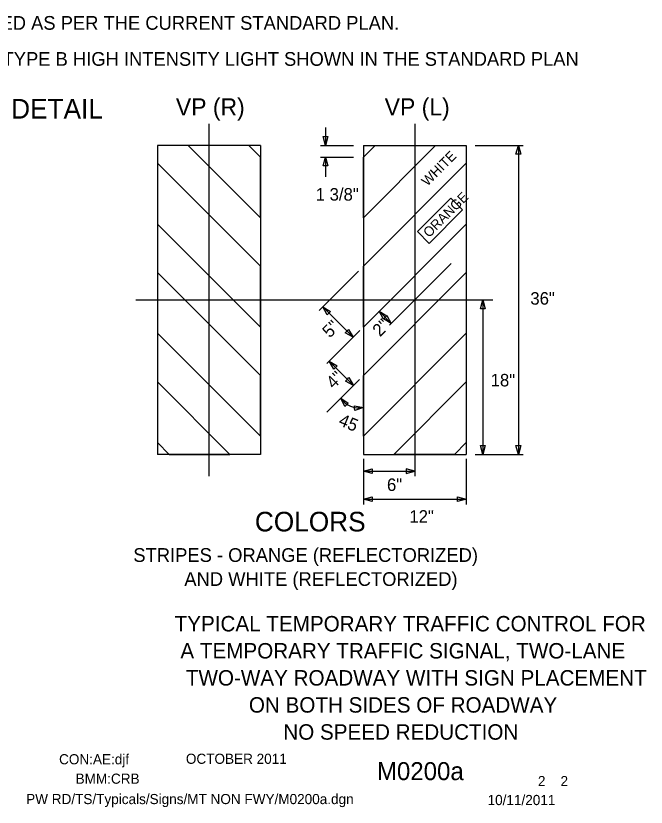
# Model space of a CAD drawing. Extents: x 16520 to 18479, y 5662 to 6927.
# Drawn here: x 18093.2 to 18479, y 5931.8 to 6415.8 of the extents above; entities that cross this region are included whole.
import ezdxf

# ---------------------------------------------------------------- set-up
doc = ezdxf.new("R2010")
doc.units = 0
for name, color, linetype in [('BORDER', 7, 'Continuous'), ('BORDER_SIGNAL_WO', 7, 'Continuous'), ('TRAFFIC_SIGNS_PR', 7, 'Continuous'), ('TYPICAL_TEXT_DIMEN_PR', 7, 'Continuous')]:
    doc.layers.add(name, color=color, linetype=linetype)

msp = doc.modelspace()

# ---------------------------------------------------------------- linework, layer by layer
at = {"layer": 'TRAFFIC_SIGNS_PR'}
for p, q in [((18242.87, 6336.58), (18179.87, 6336.58)), ((18179.87, 6336.58), (18179.87, 6147.58)), ((18242.87, 6292.31), (18198.6, 6336.58)), ((18242.87, 6329.44), (18235.73, 6336.58)), ((18242.87, 6336.58), (18242.87, 6147.58)), ((18305.9, 6336.58), (18368.9, 6336.58)), ((18305.9, 6336.58), (18305.9, 6147.58)), ((18305.9, 6329.44), (18313.04, 6336.58)), ((18305.9, 6292.31), (18350.16, 6336.58)), ((18368.9, 6336.58), (18368.9, 6147.58)), ((18242.87, 6262.61), (18179.87, 6325.61)), ((18305.9, 6262.61), (18368.9, 6325.61)), ((18242.87, 6225.49), (18179.87, 6288.49)), ((18305.9, 6225.49), (18368.9, 6288.49)), ((18315.18, 6271.9), (18324.46, 6281.18)), ((18242.87, 6195.79), (18179.87, 6258.79)), ((18305.9, 6195.79), (18368.9, 6258.79)), ((18242.87, 6158.66), (18179.87, 6221.66)), ((18305.9, 6158.66), (18368.9, 6221.66)), ((18224.26, 6147.58), (18179.87, 6191.97)), ((18324.5, 6147.58), (18368.9, 6191.97)), ((18187.14, 6147.58), (18179.87, 6154.84)), ((18361.63, 6147.58), (18368.9, 6154.84)), ((18242.87, 6147.58), (18179.87, 6147.58)), ((18305.9, 6147.58), (18368.9, 6147.58))]:
    msp.add_line(p, q, dxfattribs=at)
for points in [[(18235.73, 6336.58), (18198.6, 6336.58), (18242.87, 6292.31), (18242.87, 6329.44)], [(18313.04, 6336.58), (18350.16, 6336.58), (18305.9, 6292.31), (18305.9, 6329.44)], [(18242.87, 6262.61), (18179.87, 6325.61), (18179.87, 6288.49), (18242.87, 6225.49)], [(18305.9, 6262.61), (18368.9, 6325.61), (18368.9, 6288.49), (18305.9, 6225.49)], [(18242.87, 6195.79), (18179.87, 6258.79), (18179.87, 6221.66), (18242.87, 6158.66)], [(18305.9, 6195.79), (18368.9, 6258.79), (18368.9, 6221.66), (18305.9, 6158.66)], [(18179.87, 6191.97), (18179.87, 6154.84), (18187.14, 6147.58), (18224.26, 6147.58)], [(18368.9, 6191.97), (18368.9, 6154.84), (18361.63, 6147.58), (18324.5, 6147.58)]]:
    msp.add_lwpolyline(points, close=True, dxfattribs=at)
at = {"layer": 'TYPICAL_TEXT_DIMEN_PR'}
for p, q in [((18211.37, 6349.7), (18211.37, 6134.18)), ((18282.8, 6347.43), (18282.8, 6336.58)), ((18337.4, 6349.7), (18337.4, 6134.18)), ((18282.8, 6336.58), (18281.35, 6341.96)), ((18281.35, 6341.96), (18282.8, 6341.96)), ((18282.8, 6341.96), (18284.24, 6341.96)), ((18284.24, 6341.96), (18282.8, 6336.58)), ((18279.65, 6336.58), (18299.8, 6336.58)), ((18374.27, 6336.58), (18403.69, 6336.58)), ((18399.32, 6331.19), (18400.76, 6336.58)), ((18400.76, 6336.58), (18400.76, 6147.58)), ((18400.76, 6336.58), (18402.2, 6331.19)), ((18400.76, 6331.19), (18399.32, 6331.19)), ((18402.2, 6331.19), (18400.76, 6331.19)), ((18279.65, 6329.44), (18299.8, 6329.44)), ((18281.35, 6324.05), (18282.8, 6329.44)), ((18282.8, 6329.44), (18282.8, 6317.37)), ((18282.8, 6329.44), (18284.24, 6324.05)), ((18282.8, 6324.05), (18281.35, 6324.05)), ((18284.24, 6324.05), (18282.8, 6324.05)), ((18321.95, 6226.63), (18359.67, 6264.35)), ((18278.78, 6235.5), (18302.97, 6259.69)), ((18166.74, 6242.08), (18385.17, 6242.08)), ((18377.66, 6236.69), (18379.1, 6242.08)), ((18379.1, 6242.08), (18379.1, 6147.58)), ((18379.1, 6242.08), (18380.54, 6236.69)), ((18299.6, 6219.19), (18281.03, 6237.75)), ((18283.82, 6232.93), (18281.03, 6237.75)), ((18281.03, 6237.75), (18285.86, 6234.97)), ((18284.84, 6233.95), (18283.82, 6232.93)), ((18285.86, 6234.97), (18284.84, 6233.95)), ((18322.97, 6227.65), (18315.52, 6235.11)), ((18318.31, 6230.28), (18315.52, 6235.11)), ((18315.52, 6235.11), (18320.35, 6232.32)), ((18379.1, 6236.69), (18377.66, 6236.69)), ((18380.54, 6236.69), (18379.1, 6236.69)), ((18318.15, 6230.44), (18319.17, 6231.46)), ((18322.97, 6227.65), (18318.15, 6230.44)), ((18319.33, 6231.3), (18318.31, 6230.28)), ((18319.17, 6231.46), (18320.19, 6232.48)), ((18320.35, 6232.32), (18319.33, 6231.3)), ((18320.19, 6232.48), (18322.97, 6227.65)), ((18295.79, 6223), (18296.81, 6224.02)), ((18296.81, 6224.02), (18299.6, 6219.19)), ((18283.62, 6203.21), (18303.84, 6223.43)), ((18294.77, 6221.98), (18295.79, 6223)), ((18299.6, 6219.19), (18294.77, 6221.98)), ((18299.8, 6189.69), (18284.95, 6204.54)), ((18287.74, 6199.71), (18284.95, 6204.54)), ((18284.95, 6204.54), (18289.78, 6201.75)), ((18288.76, 6200.73), (18287.74, 6199.71)), ((18289.78, 6201.75), (18288.76, 6200.73)), ((18283.62, 6173.52), (18303.5, 6193.4)), ((18294.97, 6192.48), (18295.99, 6193.5)), ((18299.8, 6189.69), (18294.97, 6192.48)), ((18295.99, 6193.5), (18297.01, 6194.52)), ((18297.01, 6194.52), (18299.8, 6189.69)), ((18294.5, 6176.97), (18292.1, 6182)), ((18292.1, 6182), (18296.69, 6178.84)), ((18295.6, 6177.9), (18294.5, 6176.97)), ((18296.69, 6178.84), (18295.6, 6177.9)), ((18300.52, 6175.93), (18300.43, 6177.37)), ((18300.43, 6177.37), (18305.9, 6176.29)), ((18300.62, 6174.49), (18300.52, 6175.93)), ((18305.9, 6176.29), (18300.62, 6174.49)), ((18379.1, 6147.58), (18377.66, 6152.96)), ((18377.66, 6152.96), (18379.1, 6152.96)), ((18379.1, 6152.96), (18380.54, 6152.96)), ((18380.54, 6152.96), (18379.1, 6147.58)), ((18400.76, 6147.58), (18399.32, 6152.96)), ((18399.32, 6152.96), (18400.76, 6152.96)), ((18400.76, 6152.96), (18402.2, 6152.96)), ((18402.2, 6152.96), (18400.76, 6147.58)), ((18374.27, 6147.58), (18403.69, 6147.58)), ((18305.9, 6144.95), (18305.9, 6116.97)), ((18368.9, 6144.95), (18368.9, 6116.97)), ((18305.9, 6137.32), (18311.28, 6138.76)), ((18305.9, 6137.32), (18337.4, 6137.32)), ((18311.28, 6135.88), (18305.9, 6137.32)), ((18311.28, 6138.76), (18311.28, 6137.32)), ((18311.28, 6137.32), (18311.28, 6135.88)), ((18337.4, 6137.32), (18332.01, 6138.76)), ((18332.01, 6138.76), (18332.01, 6137.32)), ((18332.01, 6137.32), (18332.01, 6135.88)), ((18332.01, 6135.88), (18337.4, 6137.32)), ((18305.9, 6120.16), (18311.28, 6121.61)), ((18305.9, 6120.16), (18368.9, 6120.16)), ((18311.28, 6118.72), (18305.9, 6120.16)), ((18311.28, 6121.61), (18311.28, 6120.16)), ((18311.28, 6120.16), (18311.28, 6118.72)), ((18363.51, 6120.16), (18363.51, 6121.61)), ((18363.51, 6121.61), (18368.9, 6120.16)), ((18368.9, 6120.16), (18363.51, 6118.72)), ((18363.51, 6118.72), (18363.51, 6120.16))]:
    msp.add_line(p, q, dxfattribs=at)
msp.add_lwpolyline([(18339.06, 6283.83), (18359.48, 6304.25), (18366.67, 6297.07), (18346.24, 6276.65)], close=True, dxfattribs=at)
msp.add_arc((18303.13, 6189.12), 13.12, 212.8393, 282.1565, dxfattribs=at)

# ---------------------------------------------------------------- texts
at = {"layer": 'BORDER'}
for s, p in [('TYPICAL TEMPORARY TRAFFIC CONTROL FOR', (18190.41, 6039.32)), ('A TEMPORARY TRAFFIC SIGNAL, TWO-LANE', (18193.93, 6022.77)), ('TWO-WAY ROADWAY WITH SIGN PLACEMENT', (18197.28, 6006.22)), ('ON BOTH SIDES OF ROADWAY', (18235.85, 5989.66)), ('NO SPEED REDUCTION', (18256.91, 5973.11))]:
    msp.add_text(s, height=9.4427, dxfattribs=at).set_placement(p)
at = {"layer": 'BORDER_SIGNAL_WO'}
for s, height, p in [('CON:AE:djf', 6.2, (18119.69, 5958.06)), ('    OCTOBER 2011    ', 6.2, (18188.08, 5958.34)), ('    M0200a    ', 11, (18297.86, 5948.38)), ('BMM:CRB   ', 6.2, (18129.81, 5946.17)), (' 2    2 ', 6.2, (18410.45, 5944.7)), ('PW RD/TS/Typicals/Signs/MT NON FWY/M0200a.dgn     ', 6.2, (18099.55, 5933.71)), ('10/11/2011    ', 6.2, (18381.93, 5933.13))]:
    msp.add_text(s, height=height, dxfattribs=at).set_placement(p)
at = {"layer": 'TYPICAL_TEXT_DIMEN_PR'}
for s, height, p in [('TEMPORARY CONCRETE BARRIER SHALL BE APPLIED AS PER THE CURRENT STANDARD PLAN.', 8.4, (17801.7, 6407.29)), ('VERTICAL PANELS SHALL BE USED IN LIEU OF THE TYPE B HIGH INTENSITY LIGHT SHOWN IN THE STANDARD PLAN ', 8.4, (17801.7, 6385.24)), ('SIGN DETAIL', 12, (18046.66, 6352.97)), ('VP (R)', 10.5, (18191.18, 6354.87)), ('VP (L)', 10.5, (18318.97, 6354.87)), ('1 3/8"', 7.654, (18276.72, 6302.8)), ('36"', 7.654, (18408.1, 6239.16)), ('18"', 7.654, (18383.8, 6189.17)), ('6"', 7.654, (18320.36, 6125.22)), ('COLORS', 12, (18239.52, 6100.47)), ('12"', 7.654, (18334.07, 6105.82)), ('STRIPES - ORANGE (REFLECTORIZED)', 8.4, (18165.13, 6081.85)), ('          AND WHITE (REFLECTORIZED)', 8.4, (18165.13, 6067.15))]:
    msp.add_text(s, height=height, dxfattribs=at).set_placement(p)
for s, height, rotation, p in [('WHITE', 6, 45, (18345.09, 6311.25)), ('ORANGE', 6, 45, (18346.12, 6279.81)), ('5"', 7.654, 45, (18285.36, 6218.39)), ('2"', 7.654, 45.0095, (18316.05, 6219.13)), ('4"', 7.654, 45, (18287.71, 6187.28)), ('45', 7.655, 337.5007, (18290.18, 6165.67))]:
    msp.add_text(s, height=height, rotation=rotation, dxfattribs=at).set_placement(p)

doc.saveas('drawing.dxf')
